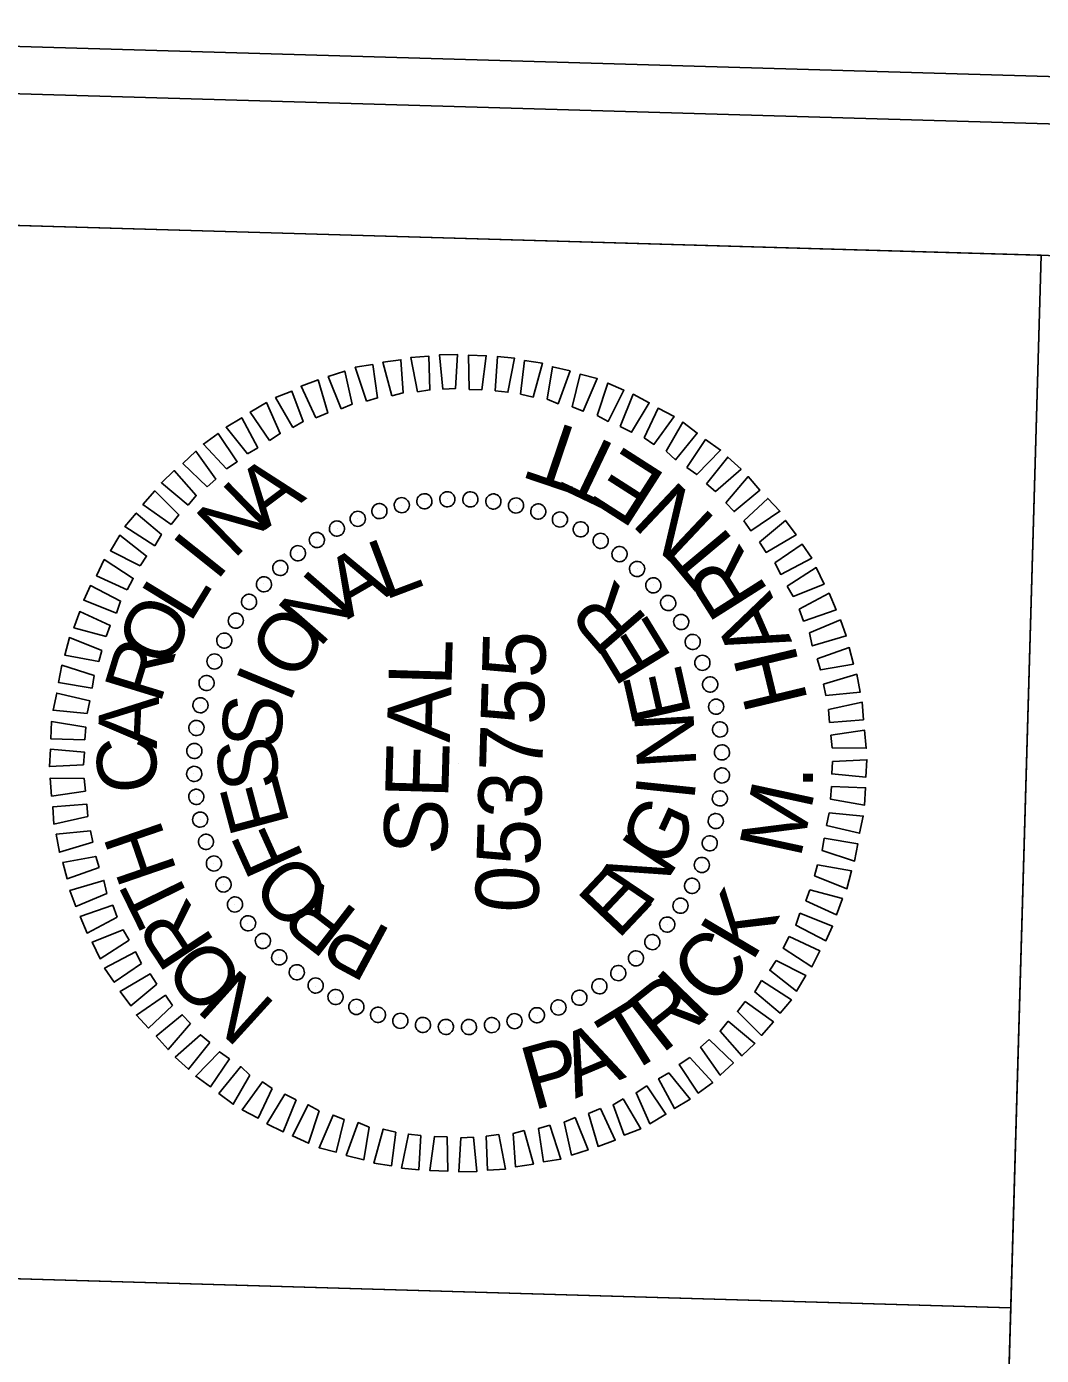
# Model space of a CAD drawing. Extents: x 2097000 to 2098148, y 684979 to 687012.
# Drawn here: x 2097114.1 to 2097210.5, y 686715.9 to 686842.1 of the extents above; entities that cross this region are included whole.
import ezdxf

# ---------------------------------------------------------------- set-up
doc = ezdxf.new("R2010")
doc.units = 0
for name, color, linetype in [('Sheet PE Seal Cell', 7, 'Continuous'), ('Sheet Plot Border Inside CELL', 7, 'Continuous'), ('Sheet Plot Border Outside CELL', 7, 'Continuous'), ('Sheet Profile CELL', 7, 'Continuous'), ('Sheet Sticker Exception Certification CELL', 7, 'Continuous')]:
    doc.layers.add(name, color=color, linetype=linetype)

msp = doc.modelspace()

# ---------------------------------------------------------------- linework, layer by layer
at = {"layer": 'Sheet PE Seal Cell'}
for p, q in [((2097147.56, 686796.1), (2097147.56, 686796.1)), ((2097149.67, 686796.63), (2097149.67, 686796.63)), ((2097151.88, 686796.97), (2097151.88, 686796.97)), ((2097154.04, 686797.21), (2097154.04, 686797.21)), ((2097156.24, 686797.19), (2097156.24, 686797.19)), ((2097158.44, 686796.98), (2097158.44, 686796.98)), ((2097160.58, 686796.57), (2097160.58, 686796.57)), ((2097162.66, 686796.06), (2097162.66, 686796.06)), ((2097145.54, 686795.35), (2097145.54, 686795.35)), ((2097164.74, 686795.3), (2097164.74, 686795.3)), ((2097143.56, 686794.41), (2097143.56, 686794.41)), ((2097166.71, 686794.34), (2097166.71, 686794.34)), ((2097141.62, 686793.32), (2097141.62, 686793.32)), ((2097168.63, 686793.28), (2097168.63, 686793.28)), ((2097139.84, 686792.12), (2097139.84, 686792.12)), ((2097170.4, 686791.98), (2097170.4, 686791.98)), ((2097138.15, 686790.67), (2097138.15, 686790.67)), ((2097172.11, 686790.58), (2097172.11, 686790.58)), ((2097136.6, 686789.16), (2097136.6, 686789.16)), ((2097173.61, 686789.04), (2097173.61, 686789.04)), ((2097135.2, 686787.45), (2097135.2, 686787.45)), ((2097175.06, 686787.34), (2097175.06, 686787.34)), ((2097133.9, 686785.69), (2097133.9, 686785.69)), ((2097176.26, 686785.56), (2097176.26, 686785.56)), ((2097132.84, 686783.77), (2097132.84, 686783.77)), ((2097177.36, 686783.62), (2097177.36, 686783.62)), ((2097131.89, 686781.8), (2097131.89, 686781.8)), ((2097178.3, 686781.65), (2097178.3, 686781.65)), ((2097131.12, 686779.72), (2097131.12, 686779.72)), ((2097179.04, 686779.62), (2097179.04, 686779.62)), ((2097130.61, 686777.63), (2097130.61, 686777.63)), ((2097179.58, 686777.51), (2097179.58, 686777.51)), ((2097130.2, 686775.49), (2097130.2, 686775.49)), ((2097179.92, 686775.3), (2097179.92, 686775.3)), ((2097129.99, 686773.3), (2097129.99, 686773.3)), ((2097155.06, 686772.12), (2097155.06, 686772.12)), ((2097180.15, 686773.14), (2097180.15, 686773.14)), ((2097129.97, 686771.1), (2097129.97, 686771.1)), ((2097180.14, 686770.94), (2097180.14, 686770.94)), ((2097130.21, 686768.94), (2097130.21, 686768.94)), ((2097179.93, 686768.74), (2097179.93, 686768.74)), ((2097130.55, 686766.73), (2097130.55, 686766.73)), ((2097179.51, 686766.61), (2097179.51, 686766.61)), ((2097131.09, 686764.61), (2097131.09, 686764.61)), ((2097179, 686764.52), (2097179, 686764.52)), ((2097131.83, 686762.59), (2097131.83, 686762.59)), ((2097178.24, 686762.44), (2097178.24, 686762.44)), ((2097132.77, 686760.61), (2097132.77, 686760.61)), ((2097177.28, 686760.47), (2097177.28, 686760.47)), ((2097133.86, 686758.68), (2097133.86, 686758.68)), ((2097176.23, 686758.55), (2097176.23, 686758.55)), ((2097135.06, 686756.89), (2097135.06, 686756.89)), ((2097174.93, 686756.78), (2097174.93, 686756.78)), ((2097136.51, 686755.2), (2097136.51, 686755.2)), ((2097173.53, 686755.07), (2097173.53, 686755.07)), ((2097138.02, 686753.66), (2097138.02, 686753.66)), ((2097171.98, 686753.57), (2097171.98, 686753.57)), ((2097139.73, 686752.26), (2097139.73, 686752.26)), ((2097170.29, 686752.12), (2097170.29, 686752.12)), ((2097141.49, 686750.95), (2097141.49, 686750.95)), ((2097168.5, 686750.92), (2097168.5, 686750.92)), ((2097143.41, 686749.9), (2097143.41, 686749.9)), ((2097166.57, 686749.82), (2097166.57, 686749.82)), ((2097145.39, 686748.94), (2097145.39, 686748.94)), ((2097147.47, 686748.18), (2097147.47, 686748.18)), ((2097162.57, 686748.14), (2097162.57, 686748.14)), ((2097164.59, 686748.88), (2097164.59, 686748.88)), ((2097149.55, 686747.67), (2097149.55, 686747.67)), ((2097151.69, 686747.26), (2097151.69, 686747.26)), ((2097153.88, 686747.04), (2097153.88, 686747.04)), ((2097156.09, 686747.03), (2097156.09, 686747.03)), ((2097158.24, 686747.27), (2097158.24, 686747.27)), ((2097160.45, 686747.6), (2097160.45, 686747.6))]:
    msp.add_line(p, q, dxfattribs=at)
for points in [[(2097146.36, 686806.49), (2097145.3, 686809.72), (2097146.96, 686809.97), (2097147.42, 686806.8)], [(2097148.78, 686807.02), (2097147.92, 686810.19), (2097149.63, 686810.44), (2097149.83, 686807.28)], [(2097151.19, 686807.4), (2097150.58, 686810.66), (2097152.29, 686810.77), (2097152.39, 686807.56)], [(2097153.6, 686807.63), (2097153.29, 686810.89), (2097154.99, 686810.94), (2097154.8, 686807.69)], [(2097156.1, 686807.6), (2097156.04, 686810.86), (2097157.74, 686810.81), (2097157.3, 686807.57)], [(2097158.59, 686807.48), (2097158.79, 686810.73), (2097160.43, 686810.58), (2097159.79, 686807.35)], [(2097160.98, 686807.16), (2097161.38, 686810.35), (2097163.07, 686810.1), (2097162.18, 686806.88)], [(2097143.94, 686805.76), (2097142.73, 686808.84), (2097144.29, 686809.35), (2097145, 686806.22)], [(2097163.52, 686806.69), (2097164.01, 686809.77), (2097165.7, 686809.37), (2097164.56, 686806.26)], [(2097165.9, 686805.97), (2097166.64, 686809.05), (2097168.28, 686808.65), (2097166.94, 686805.54)], [(2097139.38, 686803.99), (2097137.72, 686806.84), (2097139.28, 686807.44), (2097140.35, 686804.56)], [(2097141.56, 686804.92), (2097140.15, 686807.92), (2097141.77, 686808.52), (2097142.68, 686805.39)], [(2097168.28, 686805.15), (2097169.27, 686808.22), (2097170.8, 686807.53), (2097169.31, 686804.57)], [(2097137.15, 686802.75), (2097135.32, 686805.46), (2097136.85, 686806.36), (2097138.17, 686803.42)], [(2097170.45, 686804.08), (2097171.69, 686807.15), (2097173.22, 686806.35), (2097171.53, 686803.55)], [(2097135.06, 686801.51), (2097133.03, 686804.02), (2097134.51, 686804.93), (2097136.03, 686802.08)], [(2097172.72, 686803.02), (2097174.05, 686805.83), (2097175.58, 686805.04), (2097173.65, 686802.39)], [(2097174.83, 686801.76), (2097176.41, 686804.51), (2097177.78, 686803.47), (2097175.71, 686800.93)], [(2097133.07, 686800.07), (2097130.88, 686802.43), (2097132.26, 686803.44), (2097134.09, 686800.74)], [(2097176.79, 686800.2), (2097178.57, 686802.85), (2097179.99, 686801.86), (2097177.72, 686799.52)], [(2097131.22, 686798.37), (2097128.93, 686800.59), (2097130.16, 686801.75), (2097132.04, 686799.1)], [(2097178.64, 686798.64), (2097180.67, 686801.19), (2097181.94, 686800.05), (2097179.52, 686797.92)], [(2097129.42, 686796.62), (2097126.88, 686798.75), (2097128.11, 686799.91), (2097130.19, 686797.55)], [(2097180.49, 686796.84), (2097182.62, 686799.33), (2097183.73, 686798.05), (2097181.27, 686796.02)], [(2097127.81, 686794.77), (2097125.12, 686796.7), (2097126.25, 686797.97), (2097128.54, 686795.7)], [(2097182.19, 686795.14), (2097184.46, 686797.27), (2097185.62, 686796.04), (2097182.87, 686794.17)], [(2097126.25, 686792.76), (2097123.4, 686794.6), (2097124.49, 686795.87), (2097126.88, 686793.85)], [(2097183.69, 686793.1), (2097186.15, 686795.17), (2097187.16, 686793.79), (2097184.31, 686792.13)], [(2097124.85, 686790.85), (2097122.04, 686792.29), (2097122.93, 686793.76), (2097125.47, 686791.79)], [(2097185.13, 686791.15), (2097187.73, 686792.93), (2097188.64, 686791.6), (2097185.7, 686790.04)], [(2097123.63, 686788.59), (2097120.72, 686789.92), (2097121.46, 686791.45), (2097124.21, 686789.67)], [(2097186.32, 686788.92), (2097189.07, 686790.69), (2097189.82, 686789.12), (2097186.89, 686787.95)], [(2097122.61, 686786.37), (2097119.5, 686787.61), (2097120.14, 686788.99), (2097123, 686787.51)], [(2097187.45, 686786.73), (2097190.3, 686788.25), (2097190.95, 686786.68), (2097187.87, 686785.62)], [(2097121.65, 686784.14), (2097118.57, 686784.98), (2097119.12, 686786.52), (2097122.03, 686785.18)], [(2097188.44, 686784.5), (2097191.37, 686785.72), (2097191.93, 686784.2), (2097188.7, 686783.25)], [(2097120.93, 686781.76), (2097117.7, 686782.36), (2097118.14, 686784.05), (2097121.21, 686782.81)], [(2097189.17, 686782.03), (2097192.2, 686783.09), (2097192.6, 686781.53), (2097189.49, 686780.97)], [(2097120.31, 686779.23), (2097117.12, 686779.77), (2097117.42, 686781.42), (2097120.49, 686780.43)], [(2097189.75, 686779.61), (2097192.93, 686780.57), (2097193.23, 686778.86), (2097189.97, 686778.56)], [(2097119.84, 686776.84), (2097116.59, 686777.14), (2097116.94, 686778.78), (2097120.07, 686778.04)], [(2097190.23, 686777.2), (2097193.45, 686777.91), (2097193.55, 686776.25), (2097190.34, 686775.99)], [(2097119.61, 686774.35), (2097116.37, 686774.44), (2097116.46, 686776.09), (2097119.7, 686775.55)], [(2097190.46, 686774.79), (2097193.67, 686775.25), (2097193.82, 686773.54), (2097190.57, 686773.59)], [(2097119.49, 686771.95), (2097116.24, 686771.8), (2097116.34, 686773.44), (2097119.58, 686773.15)], [(2097190.63, 686772.28), (2097193.89, 686772.44), (2097193.79, 686770.79), (2097190.55, 686771.09)], [(2097119.67, 686769.45), (2097116.46, 686768.99), (2097116.31, 686770.69), (2097119.56, 686770.65)], [(2097190.51, 686769.89), (2097193.76, 686769.79), (2097193.66, 686768.14), (2097190.43, 686768.69)], [(2097119.9, 686767.04), (2097116.68, 686766.33), (2097116.58, 686767.98), (2097119.79, 686768.24)], [(2097190.29, 686767.39), (2097193.53, 686767.1), (2097193.19, 686765.46), (2097190.06, 686766.2)], [(2097120.38, 686764.62), (2097117.2, 686763.66), (2097116.9, 686765.37), (2097120.16, 686765.68)], [(2097189.82, 686765), (2097193.01, 686764.46), (2097192.71, 686762.82), (2097189.64, 686763.81)], [(2097120.96, 686762.2), (2097117.93, 686761.14), (2097117.52, 686762.7), (2097120.64, 686763.26)], [(2097189.2, 686762.47), (2097192.43, 686761.88), (2097191.98, 686760.19), (2097188.92, 686761.43)], [(2097121.69, 686759.73), (2097118.75, 686758.52), (2097118.2, 686760.03), (2097121.43, 686760.99)], [(2097188.48, 686760.09), (2097191.56, 686759.25), (2097191.01, 686757.72), (2097188.1, 686759.05)], [(2097122.68, 686757.5), (2097119.83, 686755.98), (2097119.18, 686757.55), (2097122.26, 686758.62)], [(2097187.51, 686757.87), (2097190.63, 686756.63), (2097189.99, 686755.25), (2097187.13, 686756.73)], [(2097123.81, 686755.32), (2097121.06, 686753.55), (2097120.31, 686755.12), (2097123.24, 686756.29)], [(2097186.5, 686755.65), (2097189.41, 686754.31), (2097188.67, 686752.78), (2097185.92, 686754.56)], [(2097125, 686753.08), (2097122.4, 686751.31), (2097121.48, 686752.64), (2097124.43, 686754.2)], [(2097185.28, 686753.38), (2097188.09, 686751.95), (2097187.2, 686750.48), (2097184.65, 686752.45)], [(2097126.44, 686751.14), (2097123.98, 686749.06), (2097122.97, 686750.44), (2097125.82, 686752.11)], [(2097183.88, 686751.47), (2097186.72, 686749.64), (2097185.64, 686748.37), (2097183.24, 686750.39)], [(2097127.93, 686749.1), (2097125.67, 686746.96), (2097124.51, 686748.2), (2097127.26, 686750.07)], [(2097182.32, 686749.47), (2097185.01, 686747.54), (2097183.88, 686746.27), (2097181.59, 686748.54)], [(2097129.63, 686747.4), (2097127.51, 686744.91), (2097126.4, 686746.19), (2097128.86, 686748.22)], [(2097180.71, 686747.61), (2097183.25, 686745.49), (2097182.02, 686744.32), (2097179.94, 686746.68)], [(2097131.48, 686745.59), (2097129.46, 686743.05), (2097128.19, 686744.19), (2097130.6, 686746.32)], [(2097178.91, 686745.86), (2097181.2, 686743.65), (2097179.96, 686742.48), (2097178.09, 686745.14)], [(2097133.34, 686744.04), (2097131.56, 686741.39), (2097130.14, 686742.38), (2097132.41, 686744.71)], [(2097135.29, 686742.48), (2097133.71, 686739.72), (2097132.34, 686740.76), (2097134.42, 686743.31)], [(2097177.06, 686744.17), (2097179.24, 686741.8), (2097177.86, 686740.79), (2097176.04, 686743.5)], [(2097137.41, 686741.22), (2097136.08, 686738.41), (2097134.55, 686739.2), (2097136.48, 686741.85)], [(2097175.07, 686742.72), (2097177.1, 686740.21), (2097175.62, 686739.31), (2097174.1, 686742.15)], [(2097139.68, 686740.15), (2097138.44, 686737.09), (2097136.91, 686737.88), (2097138.59, 686740.68)], [(2097172.98, 686741.48), (2097174.8, 686738.78), (2097173.28, 686737.87), (2097171.96, 686740.81)], [(2097141.85, 686739.09), (2097140.86, 686736.02), (2097139.33, 686736.71), (2097140.82, 686739.67)], [(2097168.57, 686739.31), (2097169.98, 686736.32), (2097168.36, 686735.72), (2097167.45, 686738.84)], [(2097170.74, 686740.25), (2097172.41, 686737.4), (2097170.84, 686736.79), (2097169.78, 686739.68)], [(2097144.23, 686738.27), (2097143.49, 686735.19), (2097141.85, 686735.59), (2097143.19, 686738.7)], [(2097166.19, 686738.48), (2097167.4, 686735.39), (2097165.84, 686734.89), (2097165.13, 686738.01)], [(2097146.61, 686737.55), (2097146.12, 686734.46), (2097144.43, 686734.86), (2097145.57, 686737.98)], [(2097149.14, 686737.08), (2097148.75, 686733.89), (2097147.06, 686734.13), (2097147.95, 686737.36)], [(2097151.53, 686736.76), (2097151.34, 686733.51), (2097149.69, 686733.66), (2097150.34, 686736.89)], [(2097158.94, 686736.84), (2097159.55, 686733.57), (2097157.84, 686733.47), (2097157.74, 686736.68)], [(2097161.35, 686737.22), (2097162.21, 686734.04), (2097160.5, 686733.79), (2097160.29, 686736.95)], [(2097163.77, 686737.75), (2097164.83, 686734.52), (2097163.17, 686734.27), (2097162.71, 686737.43)], [(2097154.03, 686736.63), (2097154.09, 686733.38), (2097152.39, 686733.43), (2097152.83, 686736.67)], [(2097156.53, 686736.61), (2097156.84, 686733.35), (2097155.14, 686733.3), (2097155.33, 686736.55)]]:
    msp.add_lwpolyline(points, close=True, dxfattribs=at)
for centre, major_axis in [((2097149.71, 686796.62), (-0.154, 0.703)), ((2097151.86, 686796.99), (-0.092, 0.714)), ((2097154.04, 686797.18), (-0.029, 0.719)), ((2097156.23, 686797.17), (0.033, 0.719)), ((2097158.41, 686796.97), (0.096, 0.714)), ((2097160.56, 686796.59), (0.158, 0.702)), ((2097145.53, 686795.32), (-0.274, 0.666)), ((2097147.59, 686796.06), (-0.215, 0.687)), ((2097162.67, 686796.02), (0.218, 0.686)), ((2097164.73, 686795.26), (0.277, 0.664)), ((2097143.55, 686794.4), (-0.331, 0.64)), ((2097166.71, 686794.33), (0.334, 0.638)), ((2097141.65, 686793.31), (-0.385, 0.608)), ((2097168.6, 686793.23), (0.389, 0.606)), ((2097139.85, 686792.06), (-0.437, 0.572)), ((2097170.39, 686791.97), (0.44, 0.57)), ((2097138.17, 686790.66), (-0.485, 0.532)), ((2097172.06, 686790.56), (0.488, 0.529)), ((2097136.62, 686789.11), (-0.529, 0.488)), ((2097173.6, 686789.01), (0.532, 0.485)), ((2097135.21, 686787.44), (-0.57, 0.44)), ((2097175.01, 686787.33), (0.572, 0.437)), ((2097133.95, 686785.65), (-0.606, 0.389)), ((2097176.25, 686785.53), (0.608, 0.385)), ((2097132.85, 686783.76), (-0.638, 0.334)), ((2097177.34, 686783.63), (0.64, 0.331)), ((2097131.92, 686781.78), (-0.664, 0.277)), ((2097178.26, 686781.65), (0.666, 0.274)), ((2097131.17, 686779.73), (-0.686, 0.218)), ((2097179, 686779.59), (0.687, 0.215)), ((2097130.59, 686777.62), (-0.702, 0.158)), ((2097179.57, 686777.48), (0.703, 0.154)), ((2097130.21, 686775.46), (-0.714, 0.096)), ((2097179.94, 686775.32), (0.714, 0.092)), ((2097130.01, 686773.28), (-0.719, 0.033)), ((2097180.12, 686773.14), (0.719, 0.029)), ((2097130, 686771.1), (-0.719, -0.029)), ((2097180.12, 686770.95), (0.719, -0.033)), ((2097130.19, 686768.92), (-0.714, -0.092)), ((2097179.92, 686768.77), (0.714, -0.096)), ((2097130.56, 686766.76), (-0.703, -0.154)), ((2097179.53, 686766.62), (0.702, -0.158)), ((2097131.12, 686764.65), (-0.687, -0.215)), ((2097178.96, 686764.51), (0.686, -0.218)), ((2097131.87, 686762.59), (-0.666, -0.274)), ((2097178.21, 686762.45), (0.664, -0.277)), ((2097132.78, 686760.6), (-0.64, -0.331)), ((2097177.28, 686760.47), (0.638, -0.334)), ((2097133.87, 686758.7), (-0.608, -0.385)), ((2097176.18, 686758.58), (0.606, -0.389)), ((2097135.12, 686756.91), (-0.572, -0.437)), ((2097174.92, 686756.79), (0.57, -0.44)), ((2097136.52, 686755.23), (-0.532, -0.485)), ((2097173.51, 686755.12), (0.529, -0.488)), ((2097138.07, 686753.68), (-0.488, -0.529)), ((2097171.95, 686753.58), (0.485, -0.532)), ((2097139.74, 686752.26), (-0.44, -0.57)), ((2097170.27, 686752.18), (0.437, -0.572)), ((2097141.53, 686751), (-0.389, -0.606)), ((2097143.42, 686749.91), (-0.334, -0.638)), ((2097166.58, 686749.84), (0.331, -0.64)), ((2097168.48, 686750.93), (0.385, -0.608)), ((2097145.4, 686748.97), (-0.277, -0.664)), ((2097164.59, 686748.92), (0.274, -0.666)), ((2097147.45, 686748.22), (-0.218, -0.686)), ((2097149.57, 686747.65), (-0.158, -0.702)), ((2097160.42, 686747.62), (0.154, -0.703)), ((2097162.54, 686748.18), (0.215, -0.687)), ((2097151.72, 686747.26), (-0.096, -0.714)), ((2097153.9, 686747.07), (-0.033, -0.719)), ((2097156.09, 686747.06), (0.029, -0.719)), ((2097158.27, 686747.24), (0.092, -0.714))]:
    msp.add_ellipse(centre, major_axis=major_axis, ratio=0.999708, dxfattribs=at)
at = {"layer": 'Sheet Plot Border Inside CELL'}
msp.add_lwpolyline([(2098077, 685140.47), (2098125.43, 686806.26), (2097070.77, 686836.92), (2097022.35, 685171.13)], close=True, dxfattribs=at)
at = {"layer": 'Sheet Plot Border Outside CELL'}
msp.add_lwpolyline([(2098099.07, 685126.82), (2098148, 686810.11), (2097048.47, 686842.07), (2096999.53, 685158.79)], close=True, dxfattribs=at)
at = {"layer": 'Sheet Profile CELL'}
msp.add_line((2097095.09, 686723.67), (2097207.5, 686720.4), dxfattribs=at)
for points in [[(2097072.96, 686824.36), (2097029.37, 685324.99), (2098078.93, 685294.48), (2098122.52, 686793.84)], [(2097095.09, 686723.67), (2097098, 686823.63), (2097210.45, 686820.36), (2097207.55, 686720.4)], [(2097092.19, 686623.66), (2097095.09, 686723.67), (2097207.55, 686720.4), (2097204.64, 686620.39)]]:
    msp.add_lwpolyline(points, close=True, dxfattribs=at)
at = {"layer": 'Sheet Sticker Exception Certification CELL'}
msp.add_line((2097204.64, 686620.39), (2097210.45, 686820.35), dxfattribs=at)

# ---------------------------------------------------------------- texts
at = {"layer": 'Sheet PE Seal Cell'}
for s, height, rotation, p in [('T', 6, 161.2906, (2097167.85, 686803.37)), ('T', 6, 154.4903, (2097171.46, 686801.63)), ('E', 6, 147.381, (2097174.99, 686799.38)), ('A', 5.64, 36.952, (2097136.75, 686794.26)), ('N', 5.64, 44.1537, (2097133.72, 686791.4)), ('N', 6, 136.6552, (2097179.72, 686795.19)), ('I', 5.64, 51.355, (2097132.1, 686789.29)), ('T', 6, 129.8549, (2097182.27, 686792.11)), ('L', 5.64, 20.7357, (2097148.06, 686787.58)), ('R', 6, 122.3747, (2097184.65, 686788.4)), ('A', 5.64, 30.0951, (2097144.56, 686785.73)), ('N', 5.64, 48.8114, (2097141.87, 686782.96)), ('L', 5.64, 58.5557, (2097129.59, 686785.31)), ('R', 5.64, 130.8162, (2097173.22, 686785.7)), ('A', 6, 113.5343, (2097186.8, 686783.66)), ('O', 5.64, 65.756, (2097127.61, 686780.97)), ('O', 5.64, 58.1683, (2097139.78, 686779.67)), ('E', 5.64, 121.4589, (2097175.46, 686782.08)), ('R', 5.64, 72.9559, (2097126.76, 686777.64)), ('SEAL', 5.998, 88.3348, (2097153.96, 686763.35)), ('053755', 5.998, 88.3348, (2097162.66, 686757.85)), ('H', 6, 103.5504, (2097188.32, 686777.98)), ('I', 5.64, 67.5244, (2097139.02, 686777.69)), ('E', 5.64, 102.7466, (2097177.26, 686776.72)), ('A', 5.64, 87.3551, (2097126.44, 686773.45)), ('S', 5.64, 86.2352, (2097138.19, 686773.41)), ('N', 5.64, 93.3912, (2097177.71, 686771.76)), ('C', 5.64, 94.5547, (2097126.63, 686769.49)), ('S', 5.64, 95.5904, (2097138.14, 686769.81)), ('E', 5.64, 104.9459, (2097139.09, 686766.33)), ('.', 6, 89.3162, (2097188.74, 686769.63)), ('I', 5.64, 84.036, (2097177.47, 686768.42)), ('M', 6, 77.7867, (2097187.56, 686762.95)), ('G', 5.64, 65.3251, (2097175.38, 686761.92)), ('H', 5.64, 108.9543, (2097128.4, 686761.84)), ('F', 5.64, 114.3019, (2097140.5, 686763.09)), ('N', 5.64, 55.9688, (2097173.02, 686758.19)), ('O', 5.64, 133.0161, (2097143.35, 686759.7)), ('E', 5.64, 46.6117, (2097170.23, 686755.27)), ('T', 5.64, 116.1546, (2097129.96, 686758.54)), ('R', 5.64, 142.3745, (2097145.75, 686757.88)), ('K', 6, 59.3025, (2097182.97, 686753.12)), ('R', 5.64, 123.3553, (2097132.06, 686755.08)), ('P', 5.64, 151.7337, (2097148.9, 686756.19)), ('C', 6, 49.7203, (2097179.42, 686748.73)), ('O', 5.64, 130.5566, (2097135.06, 686751.54)), ('N', 5.64, 137.7583, (2097137.89, 686749.16)), ('I', 6, 45.9184, (2097177.82, 686747.17)), ('R', 6, 38.4381, (2097174.38, 686744.42)), ('T', 6, 31.6379, (2097170.96, 686742.33)), ('A', 6, 22.7975, (2097166.19, 686740.24)), ('P', 6, 15.6882, (2097162.16, 686739.11))]:
    msp.add_text(s, height=height, rotation=rotation, dxfattribs=at).set_placement(p)
at = {"layer": 'Sheet Sticker Exception Certification CELL'}
msp.add_text('DOCUMENT NOT CONSIDERED FINAL', height=5.5, rotation=88.3348, dxfattribs=at).set_placement((2097215.59, 686641.15))

doc.saveas('drawing.dxf')
